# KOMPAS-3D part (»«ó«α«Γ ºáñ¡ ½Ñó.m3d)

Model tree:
1. Эскиз:1
2. Операция выдавливания:1
     Расстояние 1 = 4.2; Расстояние 2 = 1.6
3. Эскиз:2
4. Операция выдавливания:2
     Расстояние 1 = 0.5; Расстояние 2 = 1.6
5. Эскиз:3
6. Операция выдавливания:6
     Расстояние 1 = 0.1; Расстояние 2 = 2.4
7. Эскиз:7
8. Операция выдавливания:7
     Расстояние 1 = 0.5; Расстояние 2 = 2.4
9. Эскиз:8
10. Операция выдавливания:8
     Расстояние 1 = 4; Расстояние 2 = 2.4
11. Эскиз:9
12. Операция выдавливания:9
     Расстояние 1 = 5; Расстояние 2 = 2.4
13. Скругление:5
     Радиус = 1.5
14. Скругление:6
     Радиус = 0.2
15. Эскиз:10
16. Операция выдавливания:10
     Расстояние 1 = 5; Расстояние 2 = 2
17. Эскиз:11
18. Вырезать элемент выдавливания:2
     Расстояние 1 = 0.5
19. Эскиз:12
20. Операция выдавливания:11
     Расстояние 1 = 0.5; Расстояние 2 = 2
21. Скругление:7
     Радиус = 0.2
22. Скругление:9
     Радиус = 1
23. Эскиз:14
24. Операция выдавливания:12
     Расстояние 1 = 0.5; Расстояние 2 = 2
25. Массив по концентрической сетке:1  (with: Операция выдавливания:12)  (labels: Экземпляр ( 1, 1 ); Экземпляр ( 1, 2 ); Экземпляр ( 1, 3 ); Экземпляр ( 1, 4 ))
     N 2 = 10; Шаг 2 = 360; Номер 2 = 1
26. Скругление:10
     Радиус = 0.1
27. Скругление:11
     Радиус = 0.1
28. Эскиз:16
29. Операция выдавливания:14
     Расстояние 1 = 1.7; Расстояние 2 = 4
30. Эскиз:17
31. Операция выдавливания:15
     Расстояние 1 = 0.2; Расстояние 2 = 4
32. Эскиз:18
33. Операция выдавливания:16
     Расстояние 1 = 0.2; Расстояние 2 = 4
34. Массив по концентрической сетке:2  (with: Операция выдавливания:16)  (labels: Экземпляр ( 1, 1 ); Экземпляр ( 1, 2 ); Экземпляр ( 1, 3 ); Экземпляр ( 1, 4 ))
     N 2 = 4; Шаг 2 = 360; Номер 2 = 1
35. Эскиз:19
36. Операция выдавливания:17
     Расстояние 1 = 0.2; Расстояние 2 = 3

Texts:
  поворот задн лев
  Сплав АЛ8  ГОСТ 1583-93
